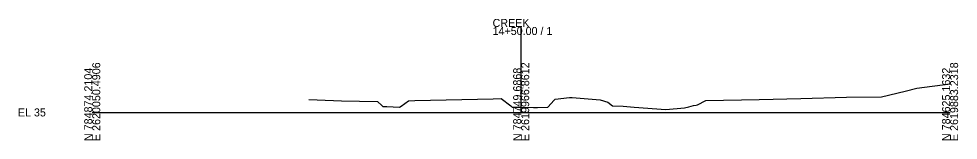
# Model space of a CAD drawing. Extents: x -26 to 303, y -10 to 5021.
# Drawn here: x -25.7 to 302.8, y 3990.3 to 4032.7 of the extents above; entities that cross this region are included whole.
import ezdxf

# ---------------------------------------------------------------- set-up
doc = ezdxf.new("R2010")
doc.units = 0
for name, color, linetype in [('RD_GPK_XS_Cell', 7, 'Continuous'), ('RD_XS_ExGround', 7, 'Continuous'), ('RD_XS_TX_Elev_EX', 7, 'Continuous')]:
    doc.layers.add(name, color=color, linetype=linetype)

msp = doc.modelspace()

# ---------------------------------------------------------------- linework, layer by layer
at = {"layer": 'RD_GPK_XS_Cell'}
for p, q in [((150, 4000), (150, 4029.84)), ((0, 4000), (150, 4000)), ((150, 4000), (300, 4000))]:
    msp.add_line(p, q, dxfattribs=at)
at = {"layer": 'RD_XS_ExGround'}
for p, q in [((284.31, 4007.48), (288.32, 4008.52)), ((288.32, 4008.52), (300, 4009.95)), ((140.15, 4004.8), (143, 4004.87)), ((143, 4004.87), (146.41, 4002.27)), ((161.85, 4004.68), (166.94, 4005.21)), ((166.94, 4005.21), (167.79, 4005.23)), ((167.79, 4005.23), (177.67, 4004.38)), ((233.2, 4004.53), (247.76, 4004.85)), ((247.76, 4004.85), (263.82, 4005.36)), ((263.82, 4005.36), (276.06, 4005.48)), ((276.06, 4005.48), (284.31, 4007.48)), ((75.72, 4004.57), (84.4, 4004.21)), ((84.4, 4004.21), (87.2, 4004.02)), ((87.2, 4004.02), (99.71, 4003.82)), ((99.71, 4003.82), (101.25, 4002.4)), ((101.25, 4002.4), (101.58, 4002.11)), ((101.58, 4002.11), (102.98, 4002.06)), ((102.98, 4002.06), (107.44, 4001.87)), ((107.44, 4001.87), (108.02, 4002.19)), ((108.02, 4002.19), (110.61, 4004.06)), ((110.61, 4004.06), (112.8, 4004.13)), ((112.8, 4004.13), (140.15, 4004.8)), ((146.41, 4002.27), (146.89, 4001.88)), ((146.89, 4001.88), (150, 4001.81)), ((150, 4001.81), (154.28, 4001.71)), ((154.28, 4001.71), (155.7, 4001.73)), ((155.7, 4001.73), (159.37, 4001.89)), ((159.37, 4001.89), (161.53, 4004.31)), ((161.53, 4004.31), (161.85, 4004.68)), ((177.67, 4004.38), (180.29, 4003.59)), ((180.29, 4003.59), (181.95, 4002.34)), ((181.95, 4002.34), (185.68, 4002.18)), ((185.68, 4002.18), (189.5, 4001.87)), ((189.5, 4001.87), (200.59, 4000.97)), ((200.59, 4000.97), (207.12, 4001.56)), ((207.12, 4001.56), (208.67, 4002)), ((208.67, 4002), (210.27, 4002.47)), ((210.27, 4002.47), (211.21, 4002.56)), ((211.21, 4002.56), (211.62, 4002.66)), ((211.62, 4002.66), (214.54, 4004.14)), ((214.54, 4004.14), (233.2, 4004.53))]:
    msp.add_line(p, q, dxfattribs=at)

# ---------------------------------------------------------------- texts
at = {"layer": 'RD_GPK_XS_Cell'}
for s, p in [('CREEK', (140, 4029.84)), ('14+50.00 / 1', (140, 4027.04)), ('EL 35', (-26, 3998.6))]:
    msp.add_text(s, height=2.8, dxfattribs=at).set_placement(p)
for s, p in [('N 784874.2104', (0, 3990)), ('E 2620050.4906', (2.8, 3990)), ('N 784749.6868', (150, 3990)), ('E 2619966.8612', (152.8, 3990)), ('N 784625.1632', (300, 3990)), ('E 2619883.2318', (302.8, 3990))]:
    msp.add_text(s, height=2.8, rotation=90, dxfattribs=at).set_placement(p)
at = {"layer": 'RD_XS_TX_Elev_EX'}
msp.add_text('36.81', height=0.8, rotation=90, dxfattribs=at).set_placement((150.7, 4006.81))

doc.saveas('drawing.dxf')
